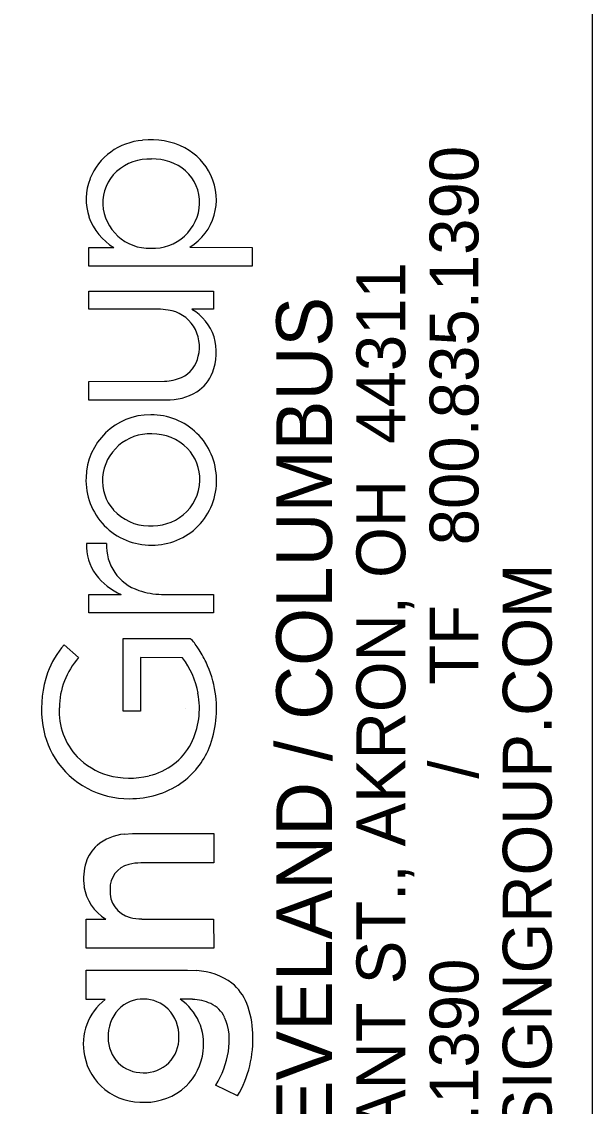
# Model space of a CAD drawing. Extents: x -0.3 to 41.5, y 0 to 22.
# Drawn here: x 32.583 to 33.166, y 3.094 to 4.202 of the extents above; entities that cross this region are included whole.
import ezdxf

# ---------------------------------------------------------------- set-up
doc = ezdxf.new("R2010")
doc.units = 0
doc.layers.add('GM_X_Adjacent_County', color=7, linetype='Continuous')
doc.layers.add('SH_Cut_Line', color=7, linetype='Continuous')

msp = doc.modelspace()

# ---------------------------------------------------------------- linework, layer by layer
at = {"layer": 'GM_X_Adjacent_County'}
msp.add_lwpolyline([(32.334, 2.5421), (32.334, 4.3266), (33.166, 4.3266), (33.166, 2.5421)], close=True, dxfattribs=at)
at = {"layer": 'SH_Cut_Line'}
for p, q in [((32.6515, 3.9521), (32.6515, 3.9711)), ((32.6515, 3.9711), (32.6771, 3.9711)), ((32.7549, 3.9713), (32.8186, 3.9711)), ((32.8186, 3.9711), (32.8184, 3.9521)), ((32.8184, 3.9521), (32.6515, 3.9521)), ((32.6515, 3.908), (32.6515, 3.9267)), ((32.6515, 3.9267), (32.7791, 3.9266)), ((32.7791, 3.9266), (32.7791, 3.908)), ((32.7249, 3.908), (32.6515, 3.908)), ((32.7328, 3.9073), (32.7249, 3.908)), ((32.7791, 3.908), (32.7569, 3.908)), ((32.6515, 3.8344), (32.7291, 3.8345)), ((32.6517, 3.8154), (32.6515, 3.8344)), ((32.7307, 3.8154), (32.6517, 3.8154)), ((32.6493, 3.6691), (32.6698, 3.6691)), ((32.6515, 3.598), (32.6515, 3.617)), ((32.6515, 3.617), (32.6848, 3.617)), ((32.726, 3.617), (32.7791, 3.617)), ((32.7791, 3.617), (32.779, 3.598)), ((32.779, 3.598), (32.6515, 3.598)), ((32.6868, 3.5718), (32.7552, 3.5719)), ((32.6868, 3.4978), (32.6868, 3.5718)), ((32.6264, 3.5655), (32.6411, 3.5524)), ((32.7045, 3.5524), (32.7043, 3.4978)), ((32.7474, 3.5523), (32.7045, 3.5524)), ((32.75, 3.5), (32.75, 3.5)), ((32.7043, 3.4978), (32.6868, 3.4978)), ((32.6878, 3.3722), (32.6963, 3.3727)), ((32.6963, 3.3727), (32.7792, 3.3727)), ((32.7792, 3.3727), (32.7792, 3.3429)), ((32.7792, 3.3429), (32.7048, 3.3428)), ((32.6489, 3.2557), (32.6489, 3.2855)), ((32.6489, 3.2855), (32.669, 3.2855)), ((32.7057, 3.2855), (32.7791, 3.2855)), ((32.7791, 3.2855), (32.7792, 3.2558)), ((32.7792, 3.2558), (32.6489, 3.2557)), ((32.6489, 3.2034), (32.6489, 3.2332)), ((32.6489, 3.2332), (32.7524, 3.2332)), ((32.7524, 3.2332), (32.7619, 3.2329)), ((32.6684, 3.2034), (32.6489, 3.2034)), ((32.7576, 3.2036), (32.7449, 3.2036)), ((32.8036, 3.1049), (32.7812, 3.116))]:
    msp.add_line(p, q, dxfattribs=at)
for points in [[(32.7549, 3.9713), (32.8186, 3.9711), (32.8184, 3.9521), (32.6515, 3.9521)], [(32.6515, 3.9521), (32.6515, 3.9711), (32.6771, 3.9711)], [(32.7328, 3.9073), (32.7249, 3.908), (32.6515, 3.908), (32.6515, 3.9267), (32.7791, 3.9266), (32.7791, 3.908), (32.7569, 3.908)], [(32.7307, 3.8154), (32.6517, 3.8154), (32.6515, 3.8344), (32.7291, 3.8345)], [(32.6493, 3.6691), (32.6698, 3.6691)], [(32.6515, 3.598), (32.6515, 3.617), (32.6848, 3.617)], [(32.726, 3.617), (32.7791, 3.617), (32.779, 3.598), (32.6515, 3.598)], [(32.7474, 3.5523), (32.7045, 3.5524), (32.7043, 3.4978), (32.6868, 3.4978), (32.6868, 3.5718), (32.7552, 3.5719)], [(32.6264, 3.5655), (32.6411, 3.5524)], [(32.6878, 3.3722), (32.6963, 3.3727), (32.7792, 3.3727), (32.7792, 3.3429), (32.7048, 3.3428)], [(32.6489, 3.2557), (32.6489, 3.2855), (32.669, 3.2855)], [(32.7057, 3.2855), (32.7791, 3.2855), (32.7792, 3.2558), (32.6489, 3.2557)], [(32.6684, 3.2034), (32.6489, 3.2034), (32.6489, 3.2332), (32.7524, 3.2332), (32.7619, 3.2329)], [(32.7576, 3.2036), (32.7449, 3.2036)], [(32.8036, 3.1049), (32.7812, 3.116)]]:
    msp.add_lwpolyline(points, dxfattribs=at)
for centre, radius, start, end in [((32.7108, 4.0182), 0.0624, 93.9866, 158.3119), ((32.7108, 4.0182), 0.0624, 93.9866, 158.3119), ((32.7156, 4.0065), 0.0746, 62.6889, 97.0135), ((32.7156, 4.0065), 0.0746, 62.6889, 97.0135), ((32.7212, 4.0191), 0.0608, 25.0657, 61.9602), ((32.7212, 4.0191), 0.0608, 25.0657, 61.9602), ((32.7138, 4.0102), 0.0513, 87.8965, 131.1812), ((32.7138, 4.0102), 0.0513, 87.8965, 131.1812), ((32.7175, 4.0102), 0.0513, 49.9089, 92.0363), ((32.7175, 4.0102), 0.0513, 49.9089, 92.0363), ((32.7092, 4.0167), 0.0434, 132.3289, 182.0949), ((32.7092, 4.0167), 0.0434, 132.3289, 182.0949), ((32.7215, 4.0173), 0.0433, 358.0487, 47.9447), ((32.7215, 4.0173), 0.0433, 358.0487, 47.9447), ((32.7245, 4.02), 0.0574, 301.9776, 25.6418), ((32.7245, 4.02), 0.0574, 301.9776, 25.6418), ((32.707, 4.0202), 0.0581, 158.656, 198.171), ((32.707, 4.0202), 0.0581, 158.656, 198.171), ((32.7135, 4.0181), 0.0478, 183.5974, 271.7045), ((32.7135, 4.0181), 0.0478, 183.5974, 271.7045), ((32.7172, 4.018), 0.0477, 267.3149, 357.4019), ((32.7172, 4.018), 0.0477, 267.3149, 357.4019), ((32.7103, 4.0243), 0.0627, 200.8399, 238.0162), ((32.7103, 4.0243), 0.0627, 200.8399, 238.0162), ((32.7271, 3.87), 0.0377, 33.5008, 81.3295), ((32.7271, 3.87), 0.0377, 33.5008, 81.3295), ((32.7324, 3.8648), 0.0496, 17.6221, 60.3897), ((32.7324, 3.8648), 0.0496, 17.6221, 60.3897), ((32.7241, 3.8695), 0.0405, 346.5618, 31.7539), ((32.7241, 3.8695), 0.0405, 346.5618, 31.7539), ((32.7234, 3.8641), 0.0584, 339.162, 15.6148), ((32.7234, 3.8641), 0.0584, 339.162, 15.6148), ((32.7337, 3.8662), 0.0304, 294.6321, 348.4863), ((32.7337, 3.8662), 0.0304, 294.6321, 348.4863), ((32.739, 3.859), 0.042, 303.1039, 338.1561), ((32.739, 3.859), 0.042, 303.1039, 338.1561), ((32.7275, 3.8808), 0.0463, 271.952, 294.0894), ((32.7275, 3.8808), 0.0463, 271.952, 294.0894), ((32.7321, 3.8726), 0.0571, 268.627, 301.4778), ((32.7321, 3.8726), 0.0571, 268.627, 301.4778), ((32.7143, 3.7348), 0.0655, 89.4821, 178.7775), ((32.7143, 3.7348), 0.0655, 89.4821, 178.7775), ((32.7158, 3.7341), 0.0662, 0.4227, 90.7613), ((32.7158, 3.7341), 0.0662, 0.4227, 90.7613), ((32.714, 3.7324), 0.0485, 87.6883, 175.017), ((32.714, 3.7324), 0.0485, 87.6883, 175.017), ((32.7166, 3.7304), 0.0505, 44.912, 90.7591), ((32.7166, 3.7304), 0.0505, 44.912, 90.7591), ((32.7196, 3.7345), 0.0455, 358.3228, 43.8349), ((32.7196, 3.7345), 0.0455, 358.3228, 43.8349), ((32.7148, 3.7334), 0.0661, 177.5373, 270.9452), ((32.7148, 3.7334), 0.0661, 177.5373, 270.9452), ((32.7108, 3.7331), 0.0453, 175.5147, 221.4205), ((32.7108, 3.7331), 0.0453, 175.5147, 221.4205), ((32.7167, 3.7327), 0.0654, 269.3083, 1.6791), ((32.7167, 3.7327), 0.0654, 269.3083, 1.6791), ((32.7193, 3.7337), 0.0457, 308.9038, 359.3095), ((32.7193, 3.7337), 0.0457, 308.9038, 359.3095), ((32.714, 3.7373), 0.0505, 222.6626, 268.3733), ((32.714, 3.7373), 0.0505, 222.6626, 268.3733), ((32.7157, 3.7386), 0.0518, 266.5531, 308.6725), ((32.7157, 3.7386), 0.0518, 266.5531, 308.6725), ((32.6988, 3.6666), 0.0495, 177.1621, 216.2802), ((32.6988, 3.6666), 0.0495, 177.1621, 216.2802), ((32.7173, 3.6664), 0.0476, 176.7699, 252.1504), ((32.7173, 3.6664), 0.0476, 176.7699, 252.1504), ((32.7098, 3.6755), 0.0637, 216.9153, 246.8862), ((32.7098, 3.6755), 0.0637, 216.9153, 246.8862), ((32.7269, 3.6917), 0.0747, 251.1388, 269.3469), ((32.7269, 3.6917), 0.0747, 251.1388, 269.3469), ((32.725, 3.5394), 0.0444, 30.9891, 47.161), ((32.725, 3.5394), 0.0444, 30.9891, 47.161), ((32.7016, 3.5019), 0.0986, 139.7948, 159.137), ((32.7016, 3.5019), 0.0986, 139.7948, 159.137), ((32.6709, 3.5002), 0.1111, 25.3031, 33.9618), ((32.6709, 3.5002), 0.1111, 25.3031, 33.9618), ((32.699, 3.5008), 0.0775, 138.258, 179.7006), ((32.699, 3.5008), 0.0775, 138.258, 179.7006), ((32.6789, 3.501), 0.0856, 10.0751, 36.8319), ((32.6789, 3.501), 0.0856, 10.0751, 36.8319), ((32.6704, 3.4999), 0.1117, 8.8034, 25.3348), ((32.6704, 3.4999), 0.1117, 8.8034, 25.3348), ((32.7187, 3.4997), 0.1154, 161.1438, 185.6281), ((32.7187, 3.4997), 0.1154, 161.1438, 185.6281), ((32.6842, 3.5006), 0.0804, 333.4669, 11.0367), ((32.6842, 3.5006), 0.0804, 333.4669, 11.0367), ((32.6756, 3.4998), 0.1065, 338.2887, 9.2855), ((32.6756, 3.4998), 0.1065, 338.2887, 9.2855), ((32.6881, 3.4973), 0.0668, 176.6658, 223.6912), ((32.6881, 3.4973), 0.0668, 176.6658, 223.6912), ((32.6934, 3.497), 0.0899, 185.5077, 212.0129), ((32.6934, 3.497), 0.0899, 185.5077, 212.0129), ((32.6987, 3.4955), 0.0652, 282.8815, 331.8147), ((32.6987, 3.4955), 0.0652, 282.8815, 331.8147), ((32.6984, 3.4917), 0.0824, 305.0306, 337.6757), ((32.6984, 3.4917), 0.0824, 305.0306, 337.6757), ((32.6921, 3.4975), 0.0891, 212.7022, 270.714), ((32.6921, 3.4975), 0.0891, 212.7022, 270.714), ((32.6905, 3.5001), 0.0704, 224.0215, 253.88), ((32.6905, 3.5001), 0.0704, 224.0215, 253.88), ((32.6932, 3.5125), 0.0831, 254.4535, 283.9512), ((32.6932, 3.5125), 0.0831, 254.4535, 283.9512), ((32.6943, 3.4998), 0.0914, 269.3273, 304.1963), ((32.6943, 3.4998), 0.0914, 269.3273, 304.1963), ((32.6922, 3.3225), 0.0499, 94.9706, 130.2248), ((32.6922, 3.3225), 0.0499, 94.9706, 130.2248), ((32.6869, 3.3309), 0.0402, 132.2238, 161.6823), ((32.6869, 3.3309), 0.0402, 132.2238, 161.6823), ((32.7022, 3.3264), 0.056, 162.274, 187.7917), ((32.7022, 3.3264), 0.056, 162.274, 187.7917), ((32.6983, 3.3169), 0.025, 103.6868, 182.214), ((32.6983, 3.3169), 0.025, 103.6868, 182.214), ((32.7045, 3.2968), 0.046, 89.6051, 105.3303), ((32.7045, 3.2968), 0.046, 89.6051, 105.3303), ((32.6937, 3.3262), 0.0476, 188.9646, 238.6987), ((32.6937, 3.3262), 0.0476, 188.9646, 238.6987), ((32.7008, 3.3138), 0.0276, 175.5844, 255.1382), ((32.7008, 3.3138), 0.0276, 175.5844, 255.1382), ((32.7053, 3.3277), 0.0421, 254.0891, 270.5284), ((32.7053, 3.3277), 0.0421, 254.0891, 270.5284), ((32.7591, 3.1679), 0.065, 53.4034, 87.4906), ((32.7591, 3.1679), 0.065, 53.4034, 87.4906), ((32.7652, 3.1804), 0.0514, 21.6075, 50.5577), ((32.7652, 3.1804), 0.0514, 21.6075, 50.5577), ((32.7029, 3.1581), 0.0569, 127.3748, 192.2247), ((32.7029, 3.1581), 0.0569, 127.3748, 192.2247), ((32.7069, 3.1693), 0.0346, 88.473, 136.4256), ((32.7069, 3.1693), 0.0346, 88.473, 136.4256), ((32.7081, 3.1696), 0.0342, 44.2719, 90.4762), ((32.7081, 3.1696), 0.0342, 44.2719, 90.4762), ((32.7142, 3.1583), 0.0547, 352.1125, 55.923), ((32.7142, 3.1583), 0.0547, 352.1125, 55.923), ((32.7567, 3.1572), 0.0463, 65.0169, 88.8011), ((32.7567, 3.1572), 0.0463, 65.0169, 88.8011), ((32.7114, 3.166), 0.0401, 137.4674, 182.3324), ((32.7114, 3.166), 0.0401, 137.4674, 182.3324), ((32.7037, 3.166), 0.04, 358.5714, 43.5376), ((32.7037, 3.166), 0.04, 358.5714, 43.5376), ((32.7626, 3.1716), 0.0309, 26.2681, 63.803), ((32.7626, 3.1716), 0.0309, 26.2681, 63.803), ((32.7307, 3.1671), 0.0884, 1.1514, 21.3627), ((32.7307, 3.1671), 0.0884, 1.1514, 21.3627), ((32.7357, 3.1615), 0.0595, 349.3073, 23.4307), ((32.7357, 3.1615), 0.0595, 349.3073, 23.4307), ((32.7054, 3.1624), 0.1138, 329.6388, 3.26), ((32.7054, 3.1624), 0.1138, 329.6388, 3.26), ((32.7065, 3.1637), 0.0351, 178.8821, 271.0837), ((32.7065, 3.1637), 0.0351, 178.8821, 271.0837), ((32.7082, 3.164), 0.0355, 268.2788, 1.5502), ((32.7082, 3.164), 0.0355, 268.2788, 1.5502), ((32.7046, 3.157), 0.0584, 190.7518, 231.2892), ((32.7046, 3.157), 0.0584, 190.7518, 231.2892), ((32.7099, 3.1571), 0.0589, 313.742, 353.8554), ((32.7099, 3.1571), 0.0589, 313.742, 353.8554), ((32.7074, 3.1633), 0.0877, 327.3149, 351.5748), ((32.7074, 3.1633), 0.0877, 327.3149, 351.5748), ((32.7095, 3.159), 0.0605, 269.6361, 312.7088), ((32.7095, 3.159), 0.0605, 269.6361, 312.7088), ((32.7063, 3.1611), 0.0627, 232.4606, 272.5902), ((32.7063, 3.1611), 0.0627, 232.4606, 272.5902)]:
    msp.add_arc(centre, radius, start, end, dxfattribs=at)

# ---------------------------------------------------------------- texts
for s, height, p in [('800.835.1390', 0.049846, (33.0497, 3.6671)), ('450 GRANT ST., AKRON, OH  44311', 0.049846, (32.9749, 2.8374)), ('AKRON / CLEVELAND / COLUMBUS', 0.056969, (32.9001, 2.638)), ('ENVDESIGNGROUP.COM', 0.049846, (33.1244, 2.8374)), ('TF', 0.04985, (33.0497, 3.5246)), ('/  ', 0.04985, (33.0497, 3.4288)), ('330.375.1390', 0.049846, (33.0497, 2.8374))]:
    msp.add_text(s, height=height, rotation=90, dxfattribs=at).set_placement(p)

doc.saveas('drawing.dxf')
